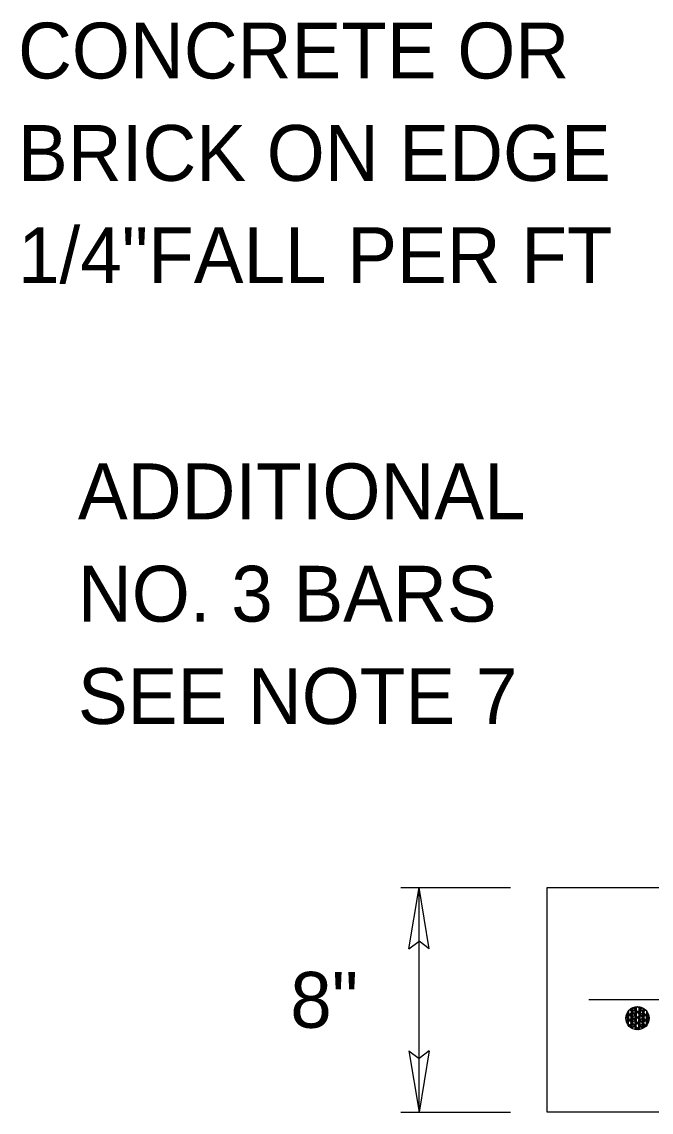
# Model space of a CAD drawing. Extents: x 26.41 to 33.74, y 20.66 to 30.6.
# Drawn here: x 26.406 to 27.082, y 23.135 to 24.307 of the extents above; entities that cross this region are included whole.
import ezdxf

# ---------------------------------------------------------------- set-up
doc = ezdxf.new("R2010")
doc.units = 0
for name, color, linetype in [('DETL-DIMS', 7, 'Continuous'), ('DETL-LINE', 7, 'Continuous'), ('DETL-NOTE', 7, 'Continuous')]:
    doc.layers.add(name, color=color, linetype=linetype)

msp = doc.modelspace()

# ---------------------------------------------------------------- linework, layer by layer
at = {"layer": 'DETL-DIMS'}
for p, q in [((26.8132, 23.3764), (26.9312, 23.3764)), ((26.8219, 23.3104), (26.8329, 23.3764)), ((26.8329, 23.135), (26.8329, 23.3764)), ((26.8439, 23.3104), (26.8329, 23.3764)), ((26.8219, 23.3104), (26.8329, 23.3187)), ((26.8439, 23.3104), (26.8329, 23.3187)), ((26.8219, 23.201), (26.8329, 23.135)), ((26.8219, 23.201), (26.8329, 23.1928)), ((26.8439, 23.201), (26.8329, 23.135)), ((26.8439, 23.201), (26.8329, 23.1928)), ((26.8132, 23.135), (26.9312, 23.135))]:
    msp.add_line(p, q, dxfattribs=at)
at = {"layer": 'DETL-LINE'}
for p, q in [((26.9705, 23.135), (26.9705, 23.3764)), ((26.9705, 23.3764), (27.1526, 23.3764)), ((27.2471, 23.2556), (27.0153, 23.2556)), ((27.0664, 23.2468), (27.0569, 23.2376)), ((27.0611, 23.2323), (27.0613, 23.2455)), ((27.0623, 23.2322), (27.0625, 23.2455)), ((27.0723, 23.2466), (27.0627, 23.2375)), ((27.0734, 23.2364), (27.0642, 23.2459)), ((27.0737, 23.2369), (27.0645, 23.2464)), ((27.0652, 23.2322), (27.0655, 23.2454)), ((27.0664, 23.2321), (27.0666, 23.2454)), ((27.0694, 23.2321), (27.0696, 23.2453)), ((27.0793, 23.2363), (27.0701, 23.2459)), ((27.0795, 23.2368), (27.0704, 23.2463)), ((27.0705, 23.2321), (27.0708, 23.2453)), ((27.0735, 23.232), (27.0737, 23.2453)), ((27.0747, 23.232), (27.0749, 23.2452)), ((27.0645, 23.2279), (27.0553, 23.2374)), ((27.0648, 23.2282), (27.0556, 23.2378)), ((27.0663, 23.2409), (27.0568, 23.2317)), ((27.0581, 23.2282), (27.0583, 23.2414)), ((27.0673, 23.2249), (27.0582, 23.2344)), ((27.0675, 23.2307), (27.0583, 23.2402)), ((27.0677, 23.2253), (27.0585, 23.2349)), ((27.0678, 23.2311), (27.0586, 23.2407)), ((27.0692, 23.238), (27.0596, 23.2288)), ((27.0693, 23.2438), (27.0597, 23.2346)), ((27.061, 23.2281), (27.0613, 23.2414)), ((27.0703, 23.2277), (27.0611, 23.2373)), ((27.0705, 23.2336), (27.0613, 23.2431)), ((27.0706, 23.2282), (27.0615, 23.2377)), ((27.0708, 23.234), (27.0616, 23.2435)), ((27.0622, 23.2281), (27.0624, 23.2413)), ((27.0721, 23.235), (27.0625, 23.2258)), ((27.0721, 23.2408), (27.0626, 23.2316)), ((27.0732, 23.2248), (27.064, 23.2343)), ((27.0733, 23.2306), (27.0641, 23.2402)), ((27.0735, 23.2252), (27.0643, 23.2347)), ((27.0736, 23.231), (27.0644, 23.2406)), ((27.0651, 23.2281), (27.0654, 23.2413)), ((27.0651, 23.2239), (27.0653, 23.2372)), ((27.075, 23.2379), (27.0655, 23.2287)), ((27.0751, 23.2437), (27.0656, 23.2345)), ((27.0662, 23.2239), (27.0665, 23.2371)), ((27.0663, 23.228), (27.0666, 23.2413)), ((27.0762, 23.2276), (27.067, 23.2372)), ((27.0763, 23.2334), (27.0671, 23.243)), ((27.0765, 23.2281), (27.0673, 23.2376)), ((27.0766, 23.2339), (27.0674, 23.2434)), ((27.0778, 23.2349), (27.0683, 23.2257)), ((27.078, 23.2407), (27.0684, 23.2316)), ((27.0692, 23.2238), (27.0694, 23.2371)), ((27.0693, 23.228), (27.0695, 23.2412)), ((27.0704, 23.2238), (27.0706, 23.2371)), ((27.0705, 23.2279), (27.0707, 23.2412)), ((27.0734, 23.2279), (27.0736, 23.2411)), ((27.0746, 23.2279), (27.0748, 23.2411)), ((27.1526, 23.135), (26.9705, 23.135))]:
    msp.add_line(p, q, dxfattribs=at)
for points in [[(27.0676, 23.2365), (27.0593, 23.2452)], [(27.0648, 23.2395), (27.0593, 23.2452)], [(27.0619, 23.2425), (27.0593, 23.2452)], [(27.0679, 23.237), (27.0597, 23.2455)], [(27.065, 23.24), (27.0597, 23.2455)], [(27.0622, 23.2429), (27.0597, 23.2455)], [(27.0681, 23.2484), (27.0598, 23.2405)], [(27.0612, 23.2364), (27.0614, 23.2466)], [(27.0613, 23.2405), (27.0614, 23.2466)], [(27.0613, 23.2446), (27.0614, 23.2466)], [(27.0624, 23.2363), (27.0626, 23.2473)], [(27.0624, 23.2405), (27.0626, 23.2473)], [(27.0625, 23.2446), (27.0626, 23.2473)], [(27.0681, 23.2484), (27.0628, 23.2433)], [(27.0705, 23.2394), (27.0629, 23.2474)], [(27.0677, 23.2424), (27.0629, 23.2474)], [(27.0648, 23.2453), (27.0629, 23.2474)], [(27.0708, 23.2398), (27.0634, 23.2476)], [(27.068, 23.2428), (27.0634, 23.2476)], [(27.0651, 23.2458), (27.0634, 23.2476)], [(27.0653, 23.2363), (27.0655, 23.2482)], [(27.0654, 23.2404), (27.0655, 23.2482)], [(27.0655, 23.2446), (27.0655, 23.2482)], [(27.0729, 23.2472), (27.0657, 23.2404)], [(27.0665, 23.2363), (27.0667, 23.2483)], [(27.0666, 23.2404), (27.0667, 23.2483)], [(27.0666, 23.2445), (27.0667, 23.2483)], [(27.0764, 23.2393), (27.0677, 23.2484)], [(27.0735, 23.2423), (27.0677, 23.2484)], [(27.0706, 23.2452), (27.0677, 23.2484)], [(27.0678, 23.2482), (27.0677, 23.2484)], [(27.0767, 23.2397), (27.0684, 23.2483)], [(27.0738, 23.2427), (27.0684, 23.2483)], [(27.071, 23.2457), (27.0684, 23.2483)], [(27.0763, 23.2449), (27.0686, 23.2374)], [(27.0694, 23.2362), (27.0696, 23.2482)], [(27.0695, 23.2404), (27.0696, 23.2482)], [(27.0696, 23.2445), (27.0696, 23.2482)], [(27.0706, 23.2362), (27.0708, 23.2479)], [(27.0706, 23.2403), (27.0708, 23.2479)], [(27.0707, 23.2444), (27.0708, 23.2479)], [(27.0736, 23.2362), (27.0738, 23.2468)], [(27.0736, 23.2403), (27.0738, 23.2468)], [(27.0737, 23.2444), (27.0738, 23.2468)], [(27.0747, 23.2361), (27.0749, 23.2461)], [(27.0748, 23.2402), (27.0749, 23.2461)], [(27.0749, 23.2444), (27.0749, 23.2461)], [(27.0635, 23.2439), (27.0552, 23.236)], [(27.0605, 23.241), (27.0552, 23.236)], [(27.0575, 23.2382), (27.0552, 23.236)], [(27.0616, 23.2308), (27.0553, 23.2374)], [(27.0588, 23.2338), (27.0553, 23.2374)], [(27.0559, 23.2367), (27.0553, 23.2374)], [(27.0619, 23.2312), (27.0554, 23.2381)], [(27.0591, 23.2342), (27.0554, 23.2381)], [(27.0562, 23.2372), (27.0554, 23.2381)], [(27.0633, 23.2381), (27.0561, 23.2312)], [(27.0604, 23.2352), (27.0561, 23.2312)], [(27.0646, 23.2337), (27.0567, 23.2418)], [(27.0618, 23.2367), (27.0567, 23.2418)], [(27.0589, 23.2396), (27.0567, 23.2418)], [(27.0569, 23.2296), (27.0571, 23.2415)], [(27.0569, 23.2296), (27.0571, 23.2373)], [(27.0569, 23.2296), (27.057, 23.2332)], [(27.057, 23.2323), (27.0572, 23.2426)], [(27.0649, 23.2341), (27.057, 23.2423)], [(27.062, 23.2371), (27.057, 23.2423)], [(27.0592, 23.2401), (27.057, 23.2423)], [(27.0571, 23.2365), (27.0572, 23.2426)], [(27.0571, 23.2406), (27.0572, 23.2426)], [(27.0581, 23.228), (27.0582, 23.2373)], [(27.0581, 23.228), (27.0582, 23.2332)], [(27.0582, 23.2323), (27.0583, 23.2442)], [(27.0582, 23.2364), (27.0583, 23.2442)], [(27.0583, 23.2406), (27.0583, 23.2442)], [(27.0662, 23.2351), (27.0584, 23.2276)], [(27.061, 23.2254), (27.0612, 23.2373)], [(27.061, 23.2254), (27.0611, 23.2331)], [(27.0621, 23.2248), (27.0624, 23.2372)], [(27.0621, 23.2248), (27.0623, 23.2331)], [(27.0766, 23.2272), (27.0699, 23.2342)], [(27.079, 23.2306), (27.07, 23.24)], [(27.0769, 23.2276), (27.0701, 23.2346)], [(27.0792, 23.2312), (27.0703, 23.2404)], [(27.0801, 23.237), (27.0713, 23.2286)], [(27.0788, 23.2415), (27.0714, 23.2344)], [(27.079, 23.2306), (27.0728, 23.2371)], [(27.0801, 23.2354), (27.0729, 23.2429)], [(27.0792, 23.2312), (27.0731, 23.2374)], [(27.0801, 23.2362), (27.0732, 23.2433)], [(27.0733, 23.2248), (27.0736, 23.237)], [(27.0801, 23.237), (27.0743, 23.2314)], [(27.0745, 23.2255), (27.0747, 23.237)], [(27.0801, 23.2354), (27.0758, 23.2399)], [(27.0801, 23.2362), (27.0761, 23.2403)], [(27.0775, 23.2283), (27.0778, 23.2411)], [(27.0775, 23.2283), (27.0777, 23.2369)], [(27.0776, 23.2319), (27.0778, 23.2431)], [(27.0777, 23.2361), (27.0778, 23.2431)], [(27.0778, 23.2402), (27.0778, 23.2431)], [(27.0787, 23.2319), (27.0789, 23.2413)], [(27.0787, 23.2301), (27.0789, 23.241)], [(27.0787, 23.2301), (27.0789, 23.2369)], [(27.0788, 23.236), (27.0789, 23.2413)], [(27.0789, 23.2402), (27.0789, 23.2413)], [(27.0628, 23.2244), (27.056, 23.2315)], [(27.0618, 23.2254), (27.056, 23.2315)], [(27.059, 23.2284), (27.056, 23.2315)], [(27.0561, 23.2314), (27.056, 23.2315)], [(27.0574, 23.2323), (27.0561, 23.2312)], [(27.0614, 23.2251), (27.0567, 23.2301)], [(27.0614, 23.2251), (27.0567, 23.2301)], [(27.0587, 23.228), (27.0567, 23.2301)], [(27.0614, 23.2251), (27.0581, 23.2286)], [(27.0632, 23.2323), (27.0584, 23.2276)], [(27.0602, 23.2294), (27.0584, 23.2276)], [(27.0628, 23.2244), (27.0584, 23.229)], [(27.0614, 23.2251), (27.0609, 23.2256)], [(27.0687, 23.2235), (27.0611, 23.2314)], [(27.0628, 23.2244), (27.0613, 23.226)], [(27.0693, 23.2236), (27.0614, 23.2319)], [(27.0691, 23.2321), (27.0616, 23.225)], [(27.0661, 23.2293), (27.0616, 23.225)], [(27.0631, 23.2264), (27.0616, 23.225)], [(27.0687, 23.2235), (27.0639, 23.2284)], [(27.0693, 23.2236), (27.0642, 23.2289)], [(27.0651, 23.2237), (27.0652, 23.233)], [(27.0749, 23.232), (27.0661, 23.2236)], [(27.0719, 23.2292), (27.0661, 23.2236)], [(27.069, 23.2263), (27.0661, 23.2236)], [(27.0662, 23.2235), (27.0664, 23.233)], [(27.0732, 23.2248), (27.0669, 23.2313)], [(27.0737, 23.225), (27.0672, 23.2317)], [(27.0692, 23.2235), (27.0694, 23.233)], [(27.0704, 23.2237), (27.0705, 23.2329)], [(27.0733, 23.2248), (27.0735, 23.2329)], [(27.0786, 23.2298), (27.0733, 23.2248)], [(27.0778, 23.229), (27.0733, 23.2248)], [(27.0748, 23.2262), (27.0733, 23.2248)], [(27.0786, 23.2298), (27.0742, 23.2256)], [(27.0745, 23.2255), (27.0747, 23.2328)], [(27.0786, 23.2298), (27.0771, 23.2284)], [(27.0775, 23.2283), (27.0776, 23.2328)], [(27.0787, 23.2301), (27.0788, 23.2328)]]:
    msp.add_lwpolyline(points, dxfattribs=at)
msp.add_circle((27.0677, 23.2359), 0.0125, dxfattribs=at)

# ---------------------------------------------------------------- texts
at = {"layer": 'DETL-NOTE'}
for s, p in [('CONCRETE OR', (26.4017, 24.2457)), ('BRICK ON EDGE', (26.4017, 24.1357)), ('1/4"FALL PER FT', (26.4017, 24.0258)), ('ADDITIONAL', (26.4661, 23.7721)), ('NO. 3 BARS', (26.4661, 23.6621)), ('SEE NOTE 7', (26.4661, 23.5521)), ('8"', (26.6944, 23.2257))]:
    msp.add_text(s, height=0.05998, dxfattribs=at).set_placement(p)

doc.saveas('drawing.dxf')
